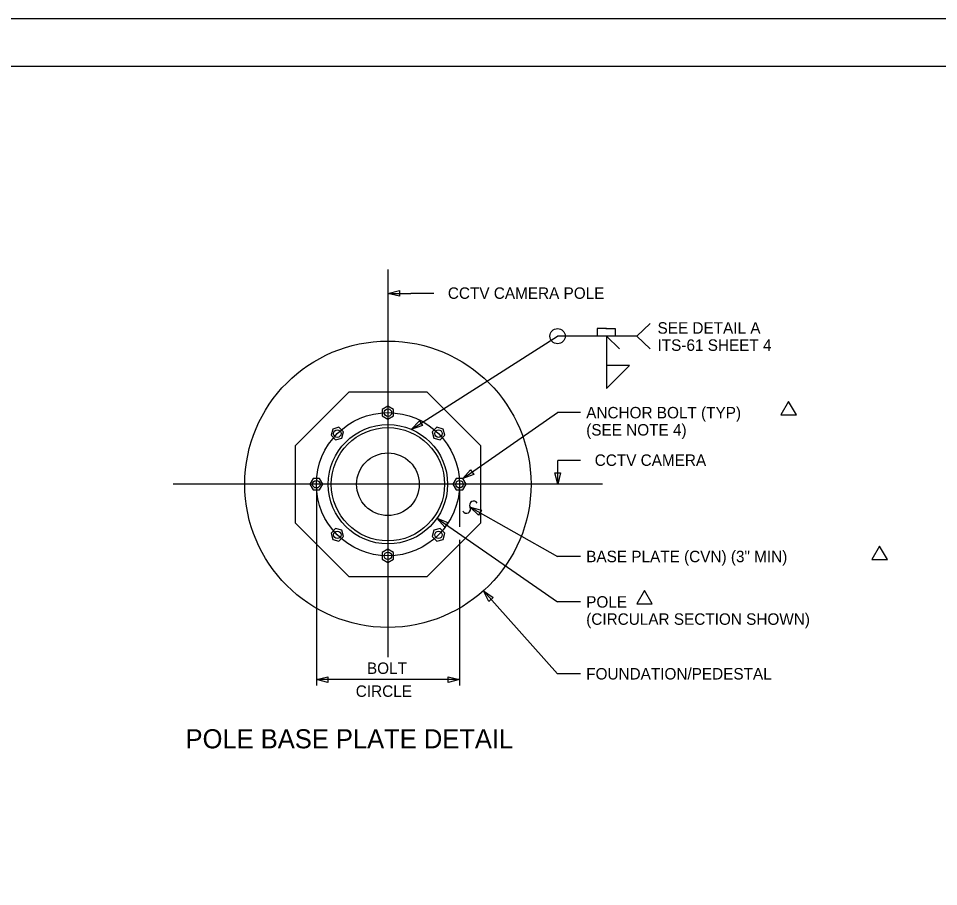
# Model space of a CAD drawing. Extents: x 1299104.6 to 1299141.4, y 239713.3 to 239735.3.
# Drawn here: x 1299118.81 to 1299128.46, y 239726.18 to 239735.27 of the extents above; entities that cross this region are included whole.
import ezdxf

# ---------------------------------------------------------------- set-up
doc = ezdxf.new("R2010")
doc.units = 0
for name, color, linetype in [('DIM TXT', 7, 'Continuous'), ('GS_plotshape_p', 7, 'Continuous'), ('Level 1', 7, 'Continuous'), ('Level 3', 7, 'Continuous'), ('Level 7', 7, 'Continuous'), ('Level 8', 7, 'Continuous')]:
    doc.layers.add(name, color=color, linetype=linetype)

msp = doc.modelspace()

# ---------------------------------------------------------------- linework, layer by layer
at = {"layer": 'DIM TXT'}
for points in [[(1299126.8037, 239731.1196), (1299126.9661, 239731.1196), (1299126.8849, 239731.2602)], [(1299127.7575, 239729.6035), (1299127.9199, 239729.6035), (1299127.8387, 239729.7441)], [(1299125.2939, 239729.1393), (1299125.4563, 239729.1393), (1299125.3751, 239729.2799)]]:
    msp.add_lwpolyline(points, close=True, dxfattribs=at)
at = {"layer": 'GS_plotshape_p'}
msp.add_lwpolyline([(1299104.6223, 239735.2729), (1299138.6223, 239735.2729), (1299138.6223, 239713.2729), (1299104.6223, 239713.2729)], close=True, dxfattribs=at)
at = {"layer": 'Level 1'}
msp.add_lwpolyline([(1299138.1223, 239713.7729), (1299106.1223, 239713.7729), (1299106.1223, 239734.7729), (1299138.1223, 239734.7729)], close=True, dxfattribs=at)
at = {"layer": 'Level 3'}
for p, q in [((1299121.7173, 239730.7989), (1299122.2798, 239731.3614)), ((1299122.2798, 239731.3614), (1299123.0923, 239731.3614)), ((1299123.0923, 239731.3614), (1299123.6548, 239730.7989)), ((1299121.7173, 239729.9864), (1299121.7173, 239730.7989)), ((1299123.6548, 239730.7989), (1299123.6548, 239729.9864)), ((1299122.2798, 239729.4239), (1299121.7173, 239729.9864)), ((1299123.6548, 239729.9864), (1299123.0923, 239729.4239)), ((1299123.0923, 239729.4239), (1299122.2798, 239729.4239))]:
    msp.add_line(p, q, dxfattribs=at)
for points in [[(1299122.686, 239731.211), (1299122.6268, 239731.1769), (1299122.6268, 239731.1085), (1299122.686, 239731.0743), (1299122.7452, 239731.1085), (1299122.7452, 239731.1769)], [(1299122.1074, 239730.9714), (1299122.0897, 239730.9053), (1299122.138, 239730.857), (1299122.204, 239730.8747), (1299122.2217, 239730.9407), (1299122.1734, 239730.989)], [(1299123.2647, 239730.9714), (1299123.1987, 239730.989), (1299123.1503, 239730.9407), (1299123.168, 239730.8747), (1299123.234, 239730.857), (1299123.2824, 239730.9053)], [(1299121.8677, 239730.3927), (1299121.9018, 239730.3335), (1299121.9702, 239730.3335), (1299122.0044, 239730.3927), (1299121.9702, 239730.4519), (1299121.9018, 239730.4519)], [(1299123.5044, 239730.3927), (1299123.4702, 239730.4519), (1299123.4018, 239730.4519), (1299123.3677, 239730.3927), (1299123.4018, 239730.3335), (1299123.4702, 239730.3335)], [(1299122.1074, 239729.814), (1299122.1734, 239729.7963), (1299122.2217, 239729.8447), (1299122.204, 239729.9107), (1299122.138, 239729.9284), (1299122.0897, 239729.8801)], [(1299123.2647, 239729.814), (1299123.2824, 239729.8801), (1299123.234, 239729.9284), (1299123.168, 239729.9107), (1299123.1503, 239729.8447), (1299123.1987, 239729.7963)], [(1299122.686, 239729.5743), (1299122.7452, 239729.6085), (1299122.7452, 239729.6769), (1299122.686, 239729.711), (1299122.6268, 239729.6769), (1299122.6268, 239729.6085)]]:
    msp.add_lwpolyline(points, close=True, dxfattribs=at)
for centre, radius in [((1299122.686, 239730.3927), 1.5), ((1299122.686, 239731.1427), 0.0391), ((1299122.686, 239730.3927), 0.625), ((1299122.686, 239730.3927), 0.5937), ((1299122.1557, 239730.923), 0.0391), ((1299123.2163, 239730.923), 0.0391), ((1299122.686, 239730.3927), 0.3281), ((1299121.936, 239730.3927), 0.0391), ((1299123.436, 239730.3927), 0.0391), ((1299122.1557, 239729.8624), 0.0391), ((1299123.2163, 239729.8624), 0.0391), ((1299122.686, 239729.6427), 0.0391)]:
    msp.add_circle(centre, radius, dxfattribs=at)
at = {"layer": 'Level 7'}
for p, q in [((1299122.686, 239732.6427), (1299122.686, 239728.5798)), ((1299124.936, 239730.3927), (1299120.436, 239730.3927))]:
    msp.add_line(p, q, dxfattribs=at)
msp.add_circle((1299122.686, 239730.3927), 0.75, dxfattribs=at)
at = {"layer": 'Level 8'}
for p, q in [((1299122.686, 239732.3927), (1299122.926, 239732.3927)), ((1299123.166, 239732.3927), (1299122.926, 239732.3927)), ((1299124.9772, 239732.0235), (1299124.8772, 239732.0235)), ((1299124.8772, 239732.0235), (1299124.8772, 239731.9443)), ((1299124.9684, 239732.0235), (1299125.0684, 239732.0235)), ((1299125.0684, 239732.0235), (1299125.0684, 239731.9443)), ((1299125.2955, 239731.9443), (1299125.4333, 239732.0784)), ((1299122.9308, 239730.9677), (1299124.464, 239731.9443)), ((1299125.2955, 239731.9443), (1299124.464, 239731.9443)), ((1299124.9762, 239731.9443), (1299124.9762, 239731.635)), ((1299124.9762, 239731.9443), (1299125.114, 239731.8102)), ((1299125.2955, 239731.9443), (1299125.4333, 239731.8102)), ((1299123.4702, 239730.4519), (1299124.464, 239731.1428)), ((1299124.704, 239731.1428), (1299124.464, 239731.1428)), ((1299124.465, 239730.3927), (1299124.465, 239730.6427)), ((1299124.705, 239730.6427), (1299124.465, 239730.6427)), ((1299121.936, 239730.3327), (1299121.936, 239728.2855)), ((1299123.436, 239730.3327), (1299123.436, 239729.9452)), ((1299123.5465, 239730.1527), (1299124.464, 239729.636)), ((1299123.1997, 239730.0366), (1299124.464, 239729.1601)), ((1299123.436, 239729.8117), (1299123.436, 239728.2855)), ((1299124.704, 239729.636), (1299124.464, 239729.636)), ((1299123.6867, 239729.2753), (1299124.464, 239728.4072)), ((1299124.704, 239729.1601), (1299124.464, 239729.1601)), ((1299123.436, 239728.3455), (1299121.936, 239728.3455)), ((1299124.704, 239728.4072), (1299124.464, 239728.4072))]:
    msp.add_line(p, q, dxfattribs=at)
for points in [[(1299122.806, 239732.3627), (1299122.686, 239732.3927), (1299122.806, 239732.4227)], [(1299124.9762, 239731.395), (1299125.2162, 239731.635), (1299124.9762, 239731.635)], [(1299123.0482, 239731.0069), (1299122.9308, 239730.9677), (1299123.0159, 239731.0575)], [(1299123.5859, 239730.4958), (1299123.4702, 239730.4519), (1299123.5516, 239730.545)], [(1299124.495, 239730.5127), (1299124.465, 239730.3927), (1299124.435, 239730.5127)], [(1299123.6363, 239730.0677), (1299123.5465, 239730.1527), (1299123.6657, 239730.12)], [(1299123.2812, 239729.9436), (1299123.1997, 239730.0366), (1299123.3154, 239729.9929)], [(1299123.7444, 239729.1658), (1299123.6867, 239729.2753), (1299123.7891, 239729.2059)], [(1299122.056, 239728.3155), (1299121.936, 239728.3455), (1299122.056, 239728.3755)], [(1299123.316, 239728.3755), (1299123.436, 239728.3455), (1299123.316, 239728.3155)]]:
    msp.add_lwpolyline(points, close=True, dxfattribs=at)
msp.add_circle((1299124.4641, 239731.9441), 0.0798, dxfattribs=at)
for centre, start, end in [((1299123.5843, 239730.1732), 28.37131, 208.37131), ((1299123.5086, 239730.1322), 208.37131, 28.37131)]:
    msp.add_arc(centre, 0.043, start, end, dxfattribs=at)

# ---------------------------------------------------------------- texts
at = {"layer": 'DIM TXT'}
for s, height, p in [('  CCTV CAMERA POLE', 0.12, (1299123.2251, 239732.3351)), ('SEE DETAIL A', 0.12, (1299125.5116, 239731.9702)), ('ITS-61 SHEET 4', 0.12, (1299125.5116, 239731.7902)), ('ANCHOR BOLT (TYP)', 0.12, (1299124.764, 239731.0828)), ('(SEE NOTE 4)', 0.12, (1299124.764, 239730.9028)), ('  CCTV CAMERA', 0.12, (1299124.764, 239730.5851)), ('BASE PLATE (CVN) (3" MIN)', 0.12, (1299124.764, 239729.576)), ('POLE', 0.12, (1299124.764, 239729.1001)), ('(CIRCULAR SECTION SHOWN)', 0.12, (1299124.764, 239728.9201)), ('BOLT', 0.12, (1299122.4663, 239728.4055)), ('FOUNDATION/PEDESTAL', 0.12, (1299124.764, 239728.3472)), ('CIRCLE', 0.12, (1299122.3492, 239728.1655)), ('POLE BASE PLATE DETAIL', 0.2, (1299120.5654, 239727.6261))]:
    msp.add_text(s, height=height, dxfattribs=at).set_placement(p)

doc.saveas('drawing.dxf')
